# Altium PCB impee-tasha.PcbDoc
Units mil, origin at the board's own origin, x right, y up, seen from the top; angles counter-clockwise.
Board outline 1900 x 2600 mil, 2 copper layers (Top Layer, Bottom Layer), stack 64.8 mil thick; 46 components, 33 nets, 154 pads, 88 vias.
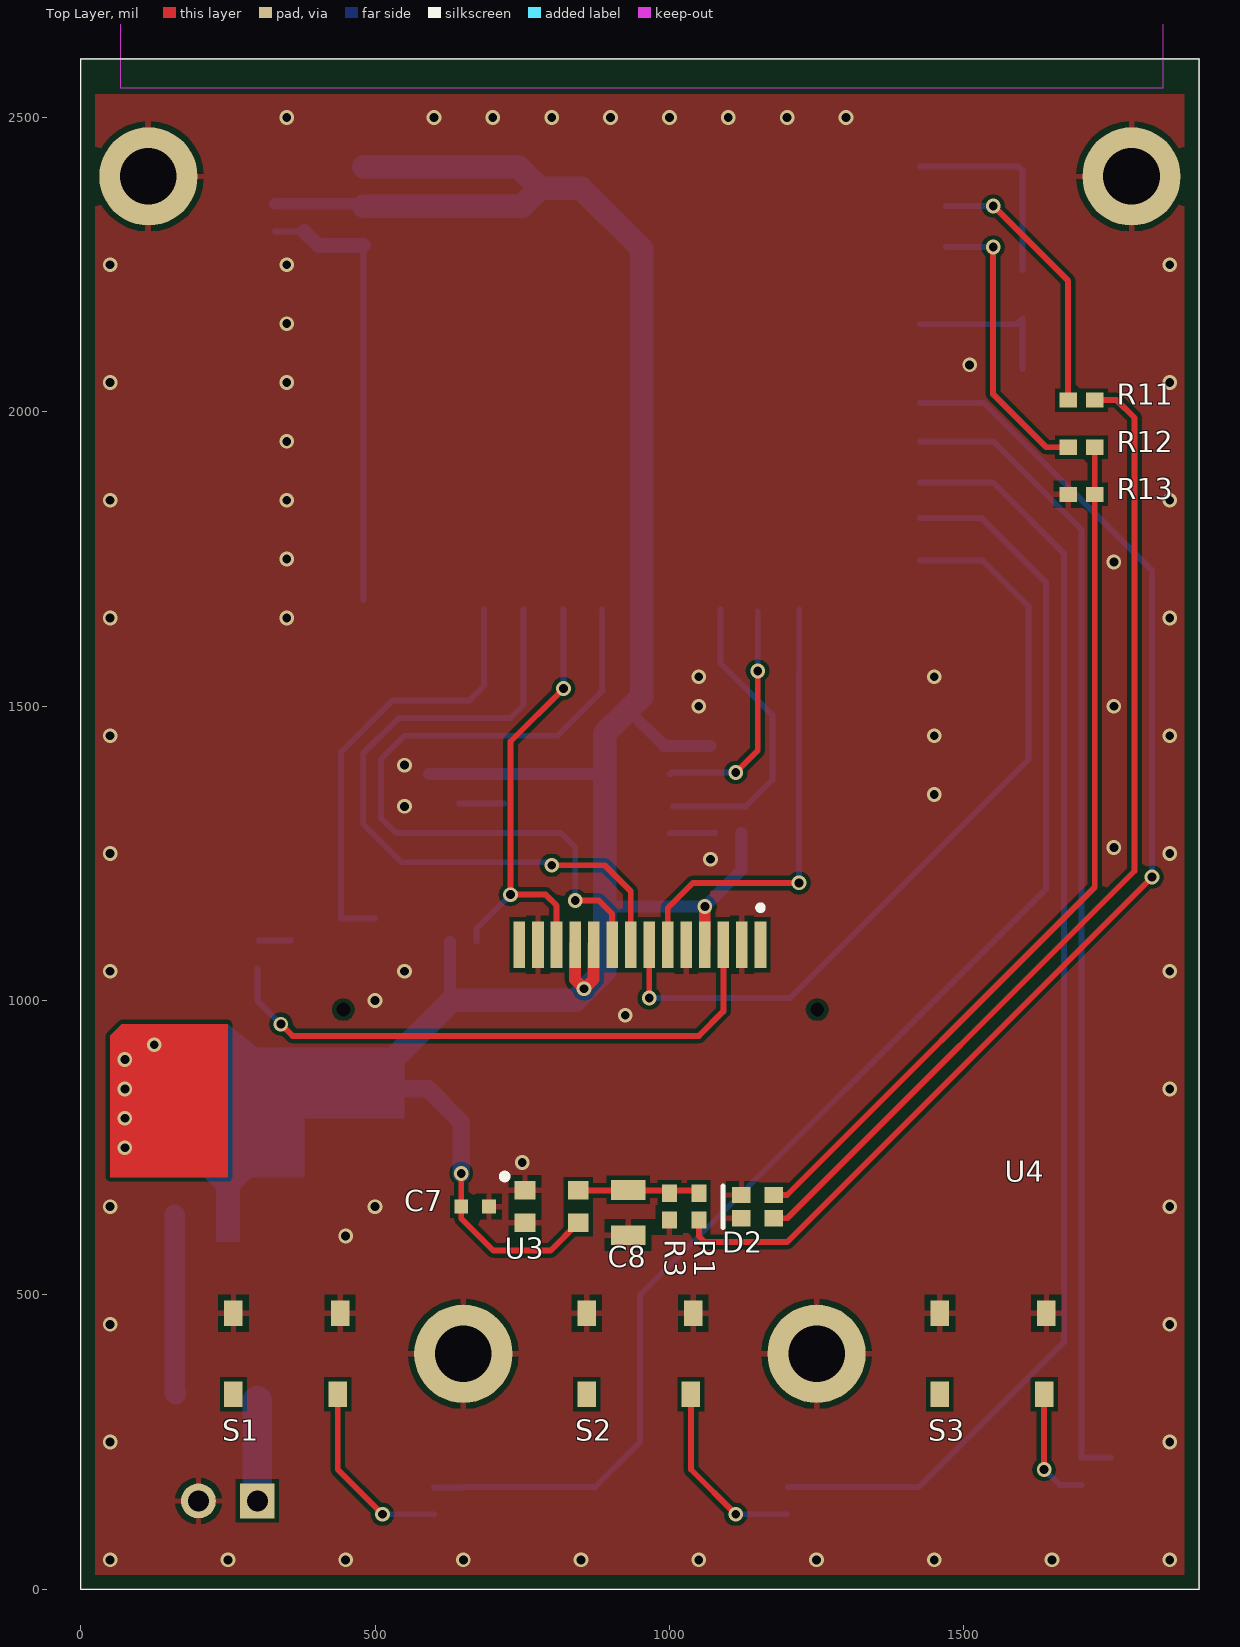
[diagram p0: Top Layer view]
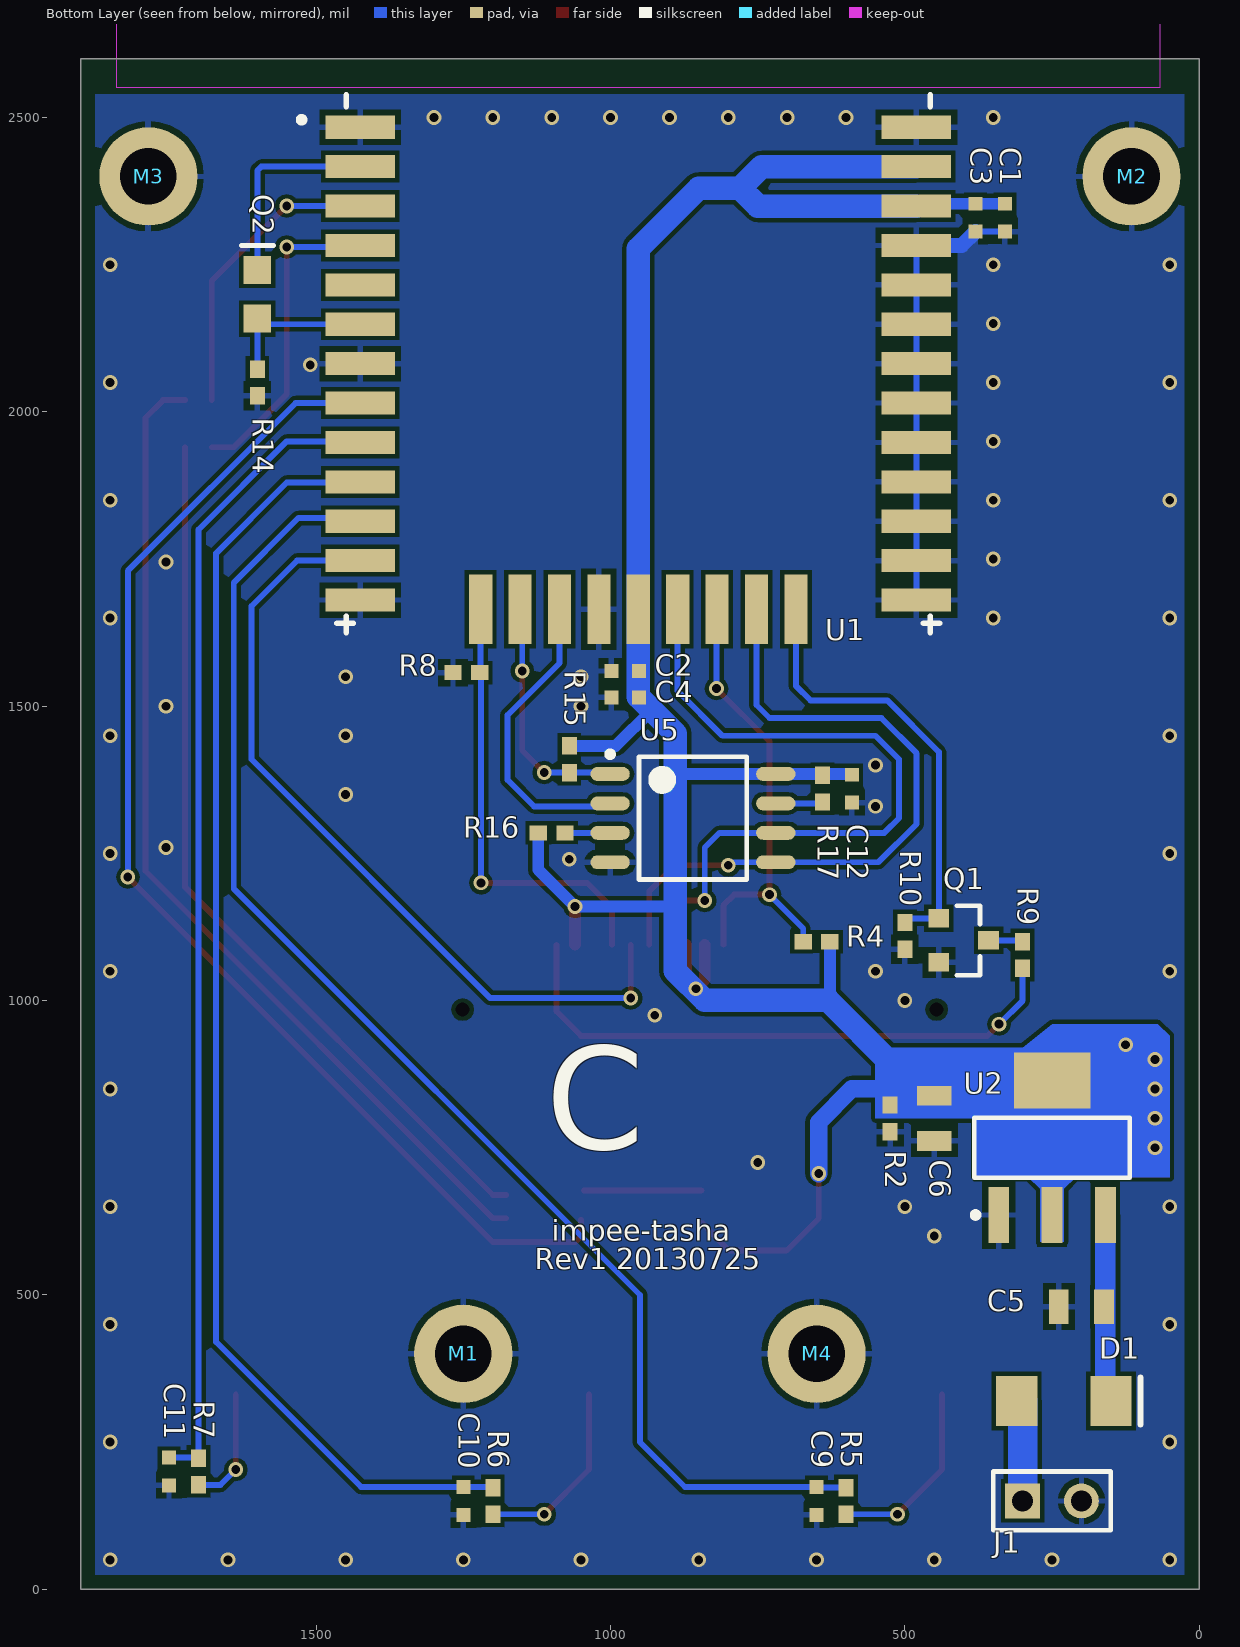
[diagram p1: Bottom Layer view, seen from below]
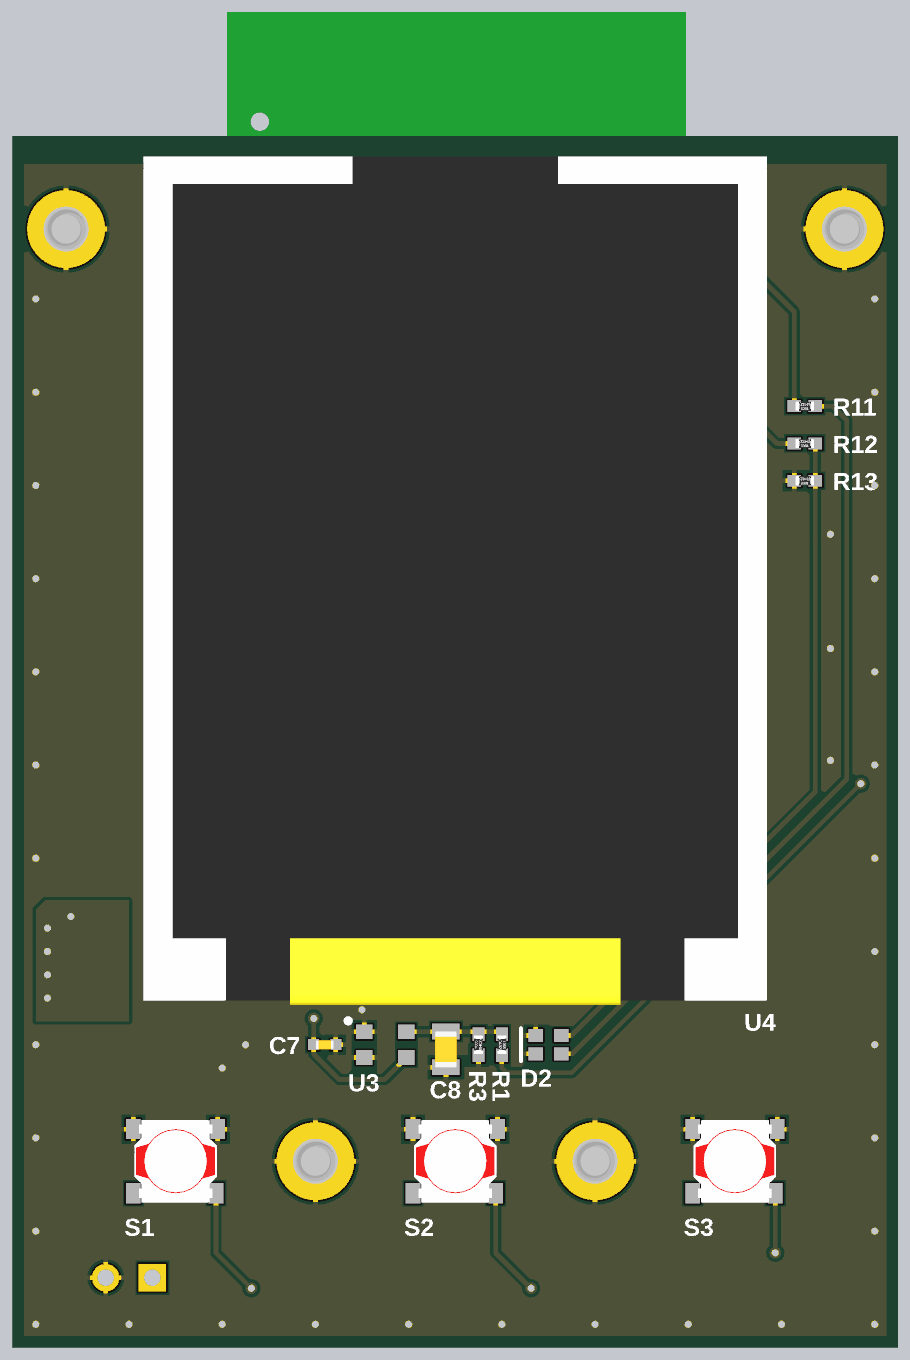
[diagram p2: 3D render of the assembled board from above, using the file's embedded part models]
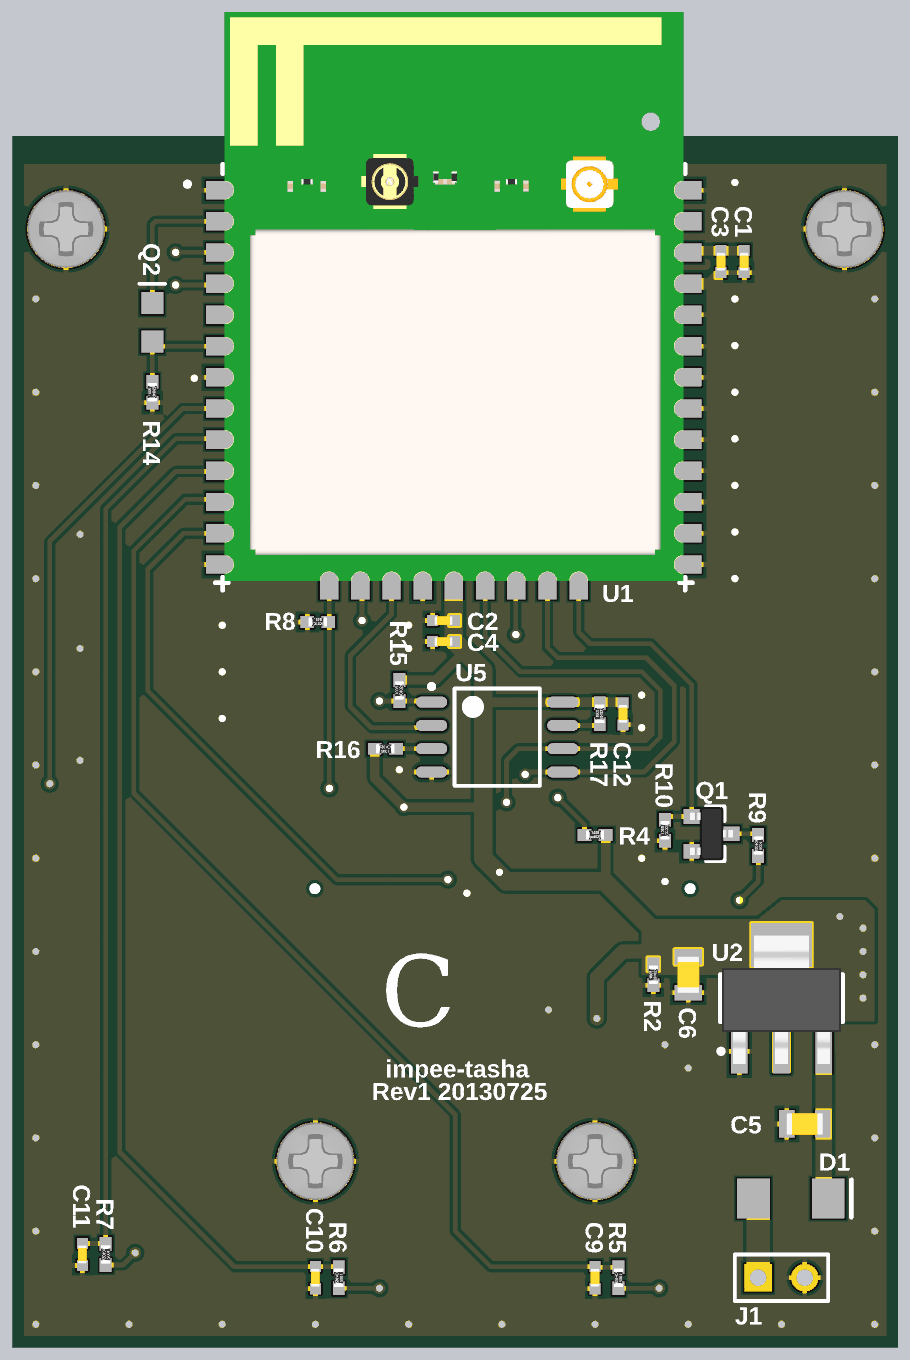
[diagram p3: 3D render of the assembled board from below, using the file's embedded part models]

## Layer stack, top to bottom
Top Layer: signal copper 1.4
Dielectric: core 62, FR-4, Dk 4.8
Bottom Layer: signal copper 1.4

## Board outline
0,0 0,2600 1900,2600 1900,0

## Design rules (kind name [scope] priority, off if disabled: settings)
Clearance [All] p1: gap=7
ComponentClearance [All] p1: gap=9 collisioncheckmode=3 verticalgap=10 showdistances=FALSE
MinimumSolderMaskSliver [All] p1: minsoldermaskwidth=1.5
PolygonConnect PolygonViaConnect [IsPolygon vs IsVia] p1: connectstyle=Direct reliefconductorwidth=10 reliefentries=4 polygonreliefangle="90 Angle" airgapwidth=10
PolygonConnect [All] p2: connectstyle=Relief reliefconductorwidth=10 reliefentries=4 polygonreliefangle="90 Angle" airgapwidth=10
RoutingVias [All] p1: holewidth=15 width=25 viastyle="Through Hole" minholewidth=10 minwidth=15 maxholewidth=15 maxwidth=25
SilkToSilkClearance [All] p1: silktosilkclearance=2.5
SilkToSolderMaskClearance [IsPad] p1: minsilkscreentomaskgap=2.5 clearancetoexposedcopper=TRUE
SolderMaskExpansion [All] p1: expansion=4
Width [All] p1: maxlimit=50 minlimit=7 preferedwidth=10
24 further rules are at their usual default settings.

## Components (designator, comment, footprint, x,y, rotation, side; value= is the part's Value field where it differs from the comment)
C1 "Ceramic Capacitor" CAPC1005X07N 330,2330 r90 bottom
C2 "Ceramic Capacitor" CAPC1005X07N 975,1560 r180 bottom
C3 "Ceramic Capacitor" CAPC1005X07N 380,2330 r90 bottom
C4 "Ceramic Capacitor" CAPC1005X07N 975,1515 r180 bottom
C5 "Ceramic Capacitor" CAPC2012X14N 200,480 r180 bottom
C6 "Ceramic Capacitor" CAPC2012X14N 450,800 r90 bottom
C7 "Ceramic Capacitor" CAPC1005X07N 670,650 r180 top
C8 "Ceramic Capacitor" CAPC2012X14N 930,640 r90 top
C9 "Ceramic Capacitor" CAPC1005X07N 650,150 r90 bottom
C10 "Ceramic Capacitor" CAPC1005X07N 1250,150 r90 bottom
C11 "Ceramic Capacitor" CAPC1005X07N 1750,200 r90 bottom
C12 "Ceramic Capacitor" CAPC1005X07N 590,1360 r90 bottom
D1 "Schottky Diode" DO-214AC 230,320 r0 bottom
D2 "LED Red and Green" LED1616X07N-REDGREEN 1150,650 r0 top
J1 "PWR2.1" HDR1X2 300,150 r180 bottom
M1 "Mounting Hole" 91772A074 1250,400 r0 bottom
M2 "Mounting Hole" 91772A074 115,2400 r0 bottom (schematic designator M1)
M3 "Mounting Hole" 91772A074 1785,2400 r0 bottom (schematic designator M1)
M4 "Mounting Hole" 91772A074 650,400 r0 bottom (schematic designator M1)
Q1 "N-Channel MOSFET" SOT95P300X130-3N 400,1102.36 r180 bottom
Q2 "PHOTOTRANSISTOR" PHOTOTRANS2012X13 1600,2200 r270 bottom
R1 "Resistor" RESC1005X04N 1050,650 r270 top
R2 "Resistor" RESC1005X04N 525,800 r90 bottom
R3 "Resistor" RESC1005X04N 1000,650 r90 top
R4 "Resistor" RESC1005X04N 650,1100 r180 bottom
R5 "Resistor" RESC1005X04N 600,150 r270 bottom
R6 "Resistor" RESC1005X04N 1200,150 r270 bottom
R7 "Resistor" RESC1005X04N 1700,200 r270 bottom
R8 "Resistor" RESC1005X04N 1245,1557.05 r180 bottom
R9 "Resistor" RESC1005X04N 300,1077.36 r270 bottom
R10 "Resistor" RESC1005X04N 500,1110 r90 bottom
R11 "Resistor" RESC1005X04N 1700,2020 r180 top
R12 "Resistor" RESC1005X04N 1700,1940 r180 top
R13 "Resistor" RESC1005X04N 1700,1860 r180 top
R14 "Resistor" RESC1005X04N 1600,2050 r90 bottom
R15 "Resistor" RESC1005X04N 1070,1410 r90 bottom
R16 "Resistor" RESC1005X04N 1100,1285 r0 bottom
R17 "Resistor" RESC1005X04N 640,1360 r90 bottom
S1 "Push Button" TL3315NF100Q 350,400 r0 top
S2 "Push Button" TL3315NF100Q 950,400 r0 top
S3 "Push Button" TL3315NF100Q 1550,400 r0 top
U1 "imp module" IMP_MODULE 1445,1645 r180 bottom locked
U2 "AP1117E33G" SOT230P700X180-4N 250,750 r90 bottom
U3 "APDS-9007" APDS-9007 800,650 r0 top
U4 "JD-T18003-T01" JD-T18003-T01 950,1650 r0 top locked
U5 "MX25L8006EM2I-12G" SOIC127P790X216-8N 860,1310 r180 bottom

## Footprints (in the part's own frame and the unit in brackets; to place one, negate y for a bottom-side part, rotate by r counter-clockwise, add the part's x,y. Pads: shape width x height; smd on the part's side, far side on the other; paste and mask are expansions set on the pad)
91772A074 [mil] "#2-56 1/8\" Phillips Machine Screw"
  round 167 hole 96: 1(0,0)
  body extent -83,-83 84,84, height 59
APDS-9007 [mm] "ChipLED, 4-Leads, Body 2x2.4mm, Manufacturer Recommended Footprint"
  rect 0.9x0.8 smd: 1(-1.15,0.7) 3(1.15,0.7) 4(1.15,-0.7) 6(-1.15,-0.7)
  silkscreen extent -2.15,1.18 -1.9,1.42, body extent -1,-1 1,1, height 1.1
CAPC1005X07N [mm] "Chip Capacitor, 2-Leads, Body 1.0x0.5mm, IPC Medium Density"
  rect 0.6x0.6 smd: 1(-0.6,0) 2(0.6,0)
  body extent -0.5,-0.25 0.5,0.25, height 0.6
CAPC2012X14N [mm] "Chip Capacitor, 2-Leads, Body 2.0x1.3mm, IPC Medium Density"
  rect 0.85x1.5 smd: 1(-0.975,0) 2(0.975,0)
  body extent -1,-0.6 1,0.6, height 1.4
DO-214AC [mm] "Diode"
  rect 1.78x2.16 smd: A(2.035,0) K(-2.035,0)
  silkscreen extent -3.3,-1.02 -3.3,1.02, body extent -2.29,-1.42 2.29,1.42, height 1.6
HDR1X2 [mm] "Connector; Header; 2 Position"
  rect 1.5x1.5 hole 0.9: 1(0,0)
  round 1.5 hole 0.9: 2(2.54,0)
  silkscreen extent -1.27,-1.27 3.81,1.27
IMP_MODULE [mm] "Imp Module, Shadow and Chase"
  rect 3x1 smd: 1(0.5,21.3) 2(0.5,19.6) 3(0.5,17.9) 4(0.5,16.2) 5(0.5,14.5) 6(0.5,12.8) 7(0.5,11.1) 8(0.5,9.4) 9(0.5,7.7) 10(0.5,6) 11(0.5,4.3) 12(0.5,2.6) 13(0.5,0.9) 23(24.5,0.9) 24(24.5,2.6) 25(24.5,4.3) 26(24.5,6) 27(24.5,7.7) 28(24.5,9.4) 29(24.5,11.1) 30(24.5,12.8) 31(24.5,14.5) 32(24.5,16.2) 33(24.5,17.9) 34(24.5,19.6) 35(24.5,21.3)
  rect 1x3 smd: 14(5.7,0.5) 15(7.4,0.5) 16(9.1,0.5) 17(10.8,0.5) 18(12.5,0.5) 19(14.2,0.5) 20(15.9,0.5) 21(17.6,0.5) 22(19.3,0.5)
  Keep-Out Layer region: -10,41 35,41 35,23 -10,23
  silkscreen extent -2.15,-0.5 25.5,22.7, body extent 0,0 25,31, height 1.8
JD-T18003-T01 [mm] "JD-T18003-T01, Color TFT LCD"
  rect 0.5x2 smd: 1(5.2,-14.1) 2(4.4,-14.1) 3(3.6,-14.1) 4(2.8,-14.1) 5(2,-14.1) 6(1.2,-14.1) 7(0.4,-14.1) 8(-0.4,-14.1) 9(-1.2,-14.1) 10(-2,-14.1) 11(-2.8,-14.1) 12(-3.6,-14.1) 13(-4.4,-14.1) 14(-5.2,-14.1)
  round 0 hole 0.6 unplated: 17(-12.8,-16.9) 18(7.65,-16.9)
  silkscreen extent 5.1,-12.6 5.3,-12.4, body extent -17,-23.23 17,23, height 2.6
LED1616X07N-REDGREEN [mm] "Bi-Color LED, 0606 (1616 metric), Red, Green"
  rect 0.8x0.7 smd: AG(0.7,-0.5) AR(0.7,0.5) KG(-0.7,-0.5) KR(-0.7,0.5)
  silkscreen extent -1.5,-0.9 -1.5,0.9, body extent -0.8,-0.8 0.8,0.8, height 0.7
PHOTOTRANS2012X13 [mm] "Phototransistor, Top View, 0805 (2012 Metric)"
  rect 1.2x1.2 smd: C(-1.05,0) E(1.05,0)
  silkscreen extent -2.1,-0.7 -2.1,0.7, body extent -1,-0.63 1,0.63, height 1.3
RESC1005X04N [mm] "Chip Resistor, 2-Leads, Body 1.0x0.5mm, IPC Medium Density"
  rect 0.75x0.65 smd: 1(-0.575,0) 2(0.575,0)
  body extent -0.5,-0.25 0.5,0.25, height 0.35
SOIC127P790X216-8N [mm] "SOIC, 8-Leads, Body 5.23x5.28mm, Pitch 1.27mm, IPC Medium Density"
  oval 1.7x0.6 smd: 1(-3.575,1.905) 2(-3.575,0.635) 3(-3.575,-0.635) 4(-3.575,-1.905) 5(3.575,-1.905) 6(3.575,-0.635) 7(3.575,0.635) 8(3.575,1.905)
  silkscreen extent -3.7,-2.65 2.33,2.88, body extent -2.7,-2.65 2.7,2.65, height 2.16
SOT95P300X130-3N [mm] "SOT-23"
  rect 0.9x0.8 smd: 1(-1.075,0.95) 2(-1.075,-0.95) 3(1.075,0)
  silkscreen extent -0.3,-1.5 0.7,1.5, body extent -1.17,-1.45 1.17,1.47, height 1
SOT230P700X180-4N [mm] "SOT223, 4-Leads, Body 6.7x7.3mm (max), Pitch 2.30mm, IPC Medium Density"
  rect 2.4x0.9 smd: 1(-2.9,2.3) 2(-2.9,0) 3(-2.9,-2.3)
  rect 2.4x3.3 smd: 4(2.9,0)
  silkscreen extent -3.02,-3.35 1.3,3.43, body extent -3.6,-3.25 3.4,3.25, height 1.64
TL3315NF100Q [mm] "Dome switch, 100gf"
  rect 0.8x1.1 smd: 1(-2.3,1.75) 2(2.3,1.75) 3(-2.3,-1.75) 4(2.2,-1.75)
  body extent -2.37,-2.25 2.38,2.25, height 0.5

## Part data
C1 C2 C12: library part CAPC00005, "CAP,X5R,1.0uF,10%,6.3V, 0402,#"
C3 C4: library part CAPC00043, "CAP,C0G,100pF,5%,50V,0402"
C5: library part CAPC00037, "CAP,X5R,10uF,10%,16V,0805,#"
C6: library part CAPC00039, "CAP,X5R,22uF,10%,6.3V,0805,#"
C7: library part CAPC00002, "CAP,X5R,0.1uF,10%,6.3V, 0402,#"
C8: library part CAPC00036, "CAP,X5R,10uF,10%,6.3V,0805,#"
C9 C10 C11: library part CAPC00026, "CAP,X7R,0.01uF,10%,16V,0402,#"
D1: library part SCHOTTKY00001, "DIODE, Schottky, 1A, 20V, DO-214AC"
D2: library part LED00012, "LED, Red and Green, 2/2V, 631/571nm, 15/20mcd, SMT"
J1: library part CON00007, "DC Power Jack, 2.1mm ID x 5.5mm OD, Panel mount, Front-side nut"
M1 M2 M3 M4: library part MNT00001, "#2-56 1/8\" Phillips Machine Screw (Stainless Steel)"
Q1: library part NFET00002, "NFET, 60V, 360mA, SOT23"
Q2: library part PHOTO00002, "Phototrans, Clear, 940nm, 0.4V, 1mA, 0805"
R1 R5 R6 R7: library part RES00024, "RES,100 Ohm,1%,0.063W,0402,#"
R2: library part RES00048, "RES,620 Ohm,5%,0.063W,0402"
R3: library part RES00042, "RES,47K,1%,0.063W,0402"
R4 R8 R10 R15 R16 R17: library part RES00001, "RES,100k,5%,0.063W,0402,#"
R9: library part RES00060, "RES,22,5%,0.063W,0402"
R11 R12: library part RES00003, "RES,1k,5%,0.063W,0402,#"
R13: library part RES00006, "RES,10k,5%,0.063W,0402,#"
R14: library part RES00008, "RES,47k,5%,0.063W,0402"
S1 S2 S3: library part BTN00004, "SPST-NO Snap Dome Switch 0.05A 15V"
U1: library part MOD00002, "Module, Electric Imp Solder Down with Antenna"
U2: library part IC00033, "IC, LDO, Fixed Output, 3.3V, 1A, SOT223"
U3: library part IC00030, "IC, Sensor,Light, Logarithmic Output, SMT4"
U4: library part DISP00001, "1.8\" Color TFT LCD, 128x160"
U5: library part IC00089, "IC, SPI Flash, 8Mbit, 86MHz"

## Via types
v1: diameter 25, hole 15, Top Layer to Bottom Layer, tented both sides, 88 vias

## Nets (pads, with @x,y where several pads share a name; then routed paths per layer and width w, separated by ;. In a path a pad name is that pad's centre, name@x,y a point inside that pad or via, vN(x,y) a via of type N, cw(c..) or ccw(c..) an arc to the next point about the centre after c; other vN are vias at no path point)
3V3: C1.2 C2.2 C3.2 C4.2 C6.2 C7.2 C12.2 R2.2 R4.2 R15.2 R16.2 R17.2 U1.18 U1.33 U1.34 U2.2 U2.4 U3.4 U4.4 U4.10 U4.11 U5.8 | length 4331.5
  Top Layer w10: v1(646.38,706.38) C7.2 646.38,630 701.1,575.28 798.11,575.28 U3.4
  Top Layer w20: U4.11 839.76,1035.24 v1(855,1020) 871.26,1036.26 U4.10 ; U4.4 v1(1060.24,1159.76)
  Bottom Layer w20: C1.2 C3.2 476.54,2353.62 U1.33 ; C12.2@591.38,1385 U5.8 885,1385 ; 627.36,1003.58 R4.2 ; 890.24,1159.76 v1(1060.24,1159.76) 1122.64,1222.17 R16.2 ; 930,1493.62 990.98,1432.64 R15.2
  Bottom Layer w30: 530,850 590,850 646.38,793.62 v1(646.38,706.38)
  Bottom Layer w40: U1.33 749.72,2349.72 780,2380 ; U1.34 743.35,2416.65 780,2380 ; 520,890 630.47,1000.47 840,1000.47 890,1050.47 890,1453.62 930,1493.62 C4.2 C4.2@951.38,1516.5 ; C4.2@952.87,1516.5 U1.18 952.87,2277.13 850,2380 780,2380
  other v1: 75,750 75,800 75,850 75,900 125,925
5V: D1.A J1.1 | length 169.9
  Bottom Layer w50: J1.1 D1.A@300,319.88
ALS_OUT: R1.2 U1.8 | length 2091.1
  Top Layer w10: R1.2 1050,600 1060,590 1200,590 v1(1820,1210)
  Bottom Layer w10: U1.8 1534.92,2015.08 1820,1730 v1(1820,1210)
BTN1: C9.2 R5.1 U1.11 | length 2386.7
  Bottom Layer w10: R5.1 C9.2@649.02,172.64 ; C9.2 873.62,173.62 950,250 950,500 1640,1190 1640,1710 1530,1820 U1.11@1425.32,1820
BTN2: C10.2 R6.1 U1.10 | length 2205.5
  Bottom Layer w10: R6.1@1200.98,173.62 C10.2 1423.62,173.62 1670,420 1670,1760 1550,1880 U1.10@1425.32,1880
BTN3: C11.2 R7.1 U1.9 | length 1963.2
  Bottom Layer w10: U1.9@1425.32,1950 1550,1950 1700,1800 R7.1 ; R7.1@1700.98,223.62 C11.2
D_C: U1.12 U4.7 | length 1379.7
  Top Layer w10: v1(965.75,1004.25) U4.7
  Bottom Layer w10: v1(965.75,1004.25) 1204.25,1004.25 1610,1410 1610,1670 1532.64,1747.36 U1.12
FLASH_CS_L: R15.1 U1.15 U5.1 | length 401
  Top Layer w10: v1(1112.64,1387.36) 1150,1424.72 v1(1150,1560)
  Bottom Layer w10: U5.1 U5.1@1003.11,1385 ; U5.1@1003.11,1387.36 R15.1 v1(1112.64,1387.36) ; v1(1150,1560) U1.15@1150,1661.02
GND: C1.1 C2.1 C3.1 C4.1 C5.1 C6.1 C7.1 C8.1 C9.1 C10.1 C11.1 C12.1 D2.KG D2.KR J1.2 M1.1 M2.1 M3.1 M4.1 Q1.2 R2.1 R3.1 R8.1 R10.1 R13.2 R14.1 S1.1 S1.2 S2.1 S2.2 S3.1 S3.2 U1.1 U1.7 U1.13 U1.17 U1.23 U1.24 U1.25 U1.26 U1.27 U1.28 U1.29 U1.30 U1.31 U1.32 U1.35 U2.1 U3.1 U3.6 U4.2 U4.5 U4.13 U5.4 | length 762.6
  Bottom Layer w10: C1.1 C3.1 ; U1.23 U1.24 U1.25 U1.26 U1.27 U1.28 U1.29 U1.30 U1.31 U1.32
  Bottom Layer w25: C3.1 403.58,2282.8 U1.32
  other v1: 50,50 250,50 450,50 650,50 850,50 1050,50 1250,50 1450,50 1650,50 1850,50 50,250 1850,250 50,450 1850,450 450,600 50,650 500,650 1850,650 750,725 1850,850 925,975 500,1000 50,1050 550,1050 1850,1050 1070,1240 50,1250 1850,1250 1755,1260 550,1330 1450,1350 550,1400 50,1450 1450,1450 1850,1450 1050,1500 1755,1500 1050,1550 1450,1550 50,1650 350,1650 1850,1650 1755,1745 350,1750 50,1850 350,1850 1850,1850 350,1950 50,2050 350,2050 1850,2050 1510,2080 350,2150 50,2250 350,2250 1850,2250 350,2500 600,2500 700,2500 800,2500 900,2500 1000,2500 1100,2500 1200,2500 1300,2500
LCD_CS_L: R4.1 U1.20 U4.12 | length 778.8
  Top Layer w10: U4.12 808.27,1161.73 790,1180 v1(730,1180) 730,1440 v1(820,1530)
  Bottom Layer w10: R4.1 672.64,1122.64 v1(730,1180) ; U1.20 820,1663.7 v1(820,1530)
LCD_RESET: R8.2 U1.14 U4.6 | length 763.4
  Top Layer w10: U4.6 997.24,1157.24 1040,1200 v1(1220,1200)
  Bottom Layer w10: v1(1220,1200) R8.2@1220,1554.68 ; R8.2@1220.59,1558.82 U1.14
LED_GREEN: R11.2 U1.3 | length 463.1
  Top Layer w10: v1(1550,2350) 1677.36,2222.64 R11.2
  Bottom Layer w10: U1.3@1470,2350 v1(1550,2350) v1@1549.72,2349.72
LED_RED: R12.2 U1.4 | length 494.6
  Top Layer w10: v1(1550,2280) 1550,2030 1640,1940 R12.2
  Bottom Layer w10: U1.4@1470,2280 v1(1550,2280)
LITE: Q1.1 R10.2 U1.22 | length 759.5
  Bottom Layer w10: R10.2@500,1139.76 Q1.1 442.32,1422.32 530,1510 660.32,1510 685.16,1534.84 U1.22
MISO: U1.16 U5.2 | length 514.1
  Bottom Layer w10: U5.2@1005.75,1330 1130,1330 1175,1375 1175,1485 1086.73,1573.27 U1.16
MOSI: U1.21 U4.8 U5.5 | length 1181.1
  Top Layer w10: v1(800,1230) 890,1230 934.25,1185.75 U4.8
  Bottom Layer w10: U1.21 752.09,1502.09 730,1480 540,1480 480,1420 480,1300 545,1235 U5.5 795,1235 v1(800,1230)
NetC5_2: C5.2 D1.K U2.3 | length 304.1
  Bottom Layer w35: D1.K@159.45,333.9 U2.3 ; D1.K@161.61,331.73 D1.K@161.61,333.9
NetC8_2: C8.2 R1.1 R3.2 U3.3 | length 199.8
  Top Layer w10: U3.3 R1.1@1045.08,677.56
NetD2_AG: D2.AG R11.1 | length 1706.5
  Top Layer w10: D2.AG 1200.32,630.32 1790,1220 1790,1990 1760,2020 R11.1
NetD2_AR: D2.AR R12.1 R13.1 | length 1509.1
  Top Layer w10: D2.AR 1199.68,669.68 1722.64,1192.64 R13.1 R12.1
NetQ1_3: Q1.3 R9.1 | length 55.3
  Bottom Layer w10: R9.1@302.36,1102.36 Q1.3
NetR5_2: R5.2 S1.4 | length 322.6
  Top Layer w10: S1.4 436.61,203.39 v1(512.64,127.36)
  Bottom Layer w10: v1(512.64,127.36) R5.2
NetR6_2: R6.2 S2.4 | length 322.6
  Top Layer w10: S2.4 1036.61,203.39 v1(1112.64,127.36)
  Bottom Layer w10: v1(1112.64,127.36) R6.2
NetR7_2: R7.2 S3.4 | length 201.9
  Top Layer w10: v1(1636.61,203.39) S3.4
  Bottom Layer w10: v1(1636.61,203.39) 1662.64,177.36 R7.2
NetR9_2: R9.2 U4.3 | length 1001.7
  Top Layer w10: v1(340,960) 360,940 1050,940 1091.73,981.73 U4.3
  Bottom Layer w10: R9.2 300,1000 v1(340,960)
NetR16_1: R16.1 U5.3 | length 76.6
  Bottom Layer w10: U5.3 R16.1
NetR17_1: R17.1 U5.7 | length 76.9
  Bottom Layer w10: R17.1@642.36,1335 U5.7
NewNet1: S2.3
NewNet2: S1.3
NewNet3: S3.3
OPTO_BIAS: Q2.C U1.2 | length 346.1
  Bottom Layer w10: U1.2 1593.35,2416.65 1600,2410 Q2.C
OPTO_IN: Q2.E R14.2 U1.6 | length 264.7
  Bottom Layer w10: U1.6 1590.28,2148.94 Q2.E R14.2
SCLK: U1.19 U4.9 U5.6 | length 1228
  Top Layer w10: v1(840,1170) 880,1170 902.76,1147.24 U4.9
  Bottom Layer w10: v1(840,1170) 840,1260 815,1285 U5.6 535,1285 510,1310 510,1410 550,1450 810,1450 885.94,1525.94 U1.19
pads on no net: U1.5 U4.1 U4.14 U4.17 U4.18

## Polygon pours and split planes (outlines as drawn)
GND on Top Layer "Top GND" (solid, remove dead copper, pour order 4): 25,2540 1875,2540 1875,25 25,25
GND on Bottom Layer "Bottom GND" (solid, remove dead copper, pour order 2): 25,2540 1875,2540 1875,25 25,25

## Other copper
Top Layer:
  region net 3V3: 50,700 50,940 70,960 250,960 250,700
Bottom Layer:
  region net 3V3: 270,590 230,590 230,680 210,700 50,700 50,940 70,960 250,960 300,920 530,920 550,900 550,800 380,800 380,700 290,700 270,680

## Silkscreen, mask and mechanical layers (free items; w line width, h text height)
Top Overlay:
  the board outline again, w1
Bottom Overlay:
  text "C" at 1110,690 h300
  text "impee-tasha" at 1100,580 h60
  text "Rev1 20130725" at 1128.65,531.35 h60
Drill Drawing:
  text ".Legend" at 2375,25 h60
